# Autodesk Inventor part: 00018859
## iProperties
Created: 2011-05
Part Number: 00018859
Document SubType Name: Modeling
Designer: Administrator
Density: 2.71 g/cm^3
Material: Aluminum-6061
Mass: 38.4372 g
Surface Area: 70.14 cm^2
Volume: 14.1835 cm^3
Author: Administrator
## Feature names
1. Base1
